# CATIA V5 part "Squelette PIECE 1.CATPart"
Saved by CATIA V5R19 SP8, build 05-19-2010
Part number: Squelette PIECE 1
Publications: "Droite.3", "Droite.2", "Droite.1", "Plan.1", "Point.6", "Point.7"
Bounding box of the stored display mesh (mm): x -17 to 0, y 0 to 0, z 0 to 9
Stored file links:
  C:\Users\ThinkMotion\Desktop\EU_thinkMotion\iao\IAO_MMS_Groupe3\jbuffard\jbuffard\Squelette PIECE 1.CATPart
  C:\Users\ThinkMotion\Desktop\EU_thinkMotion\iao\IAO_MMS_Groupe3\jbuffard\jbuffard\Mecanisme a coulisse a quatre elements de la griffe d'une camera.CATProduct
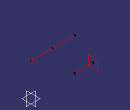
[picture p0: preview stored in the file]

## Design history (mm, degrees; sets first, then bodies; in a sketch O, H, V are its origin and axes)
Set1
  Point1 to Point5: linked copy from another document
  Plane1: linked copy from another document
Set2 "Set géométrique.3"
  Line1: type PtPt, FirstPoint Point1, SecondPoint Point2
  Line2: type PtPt, FirstPoint Point3, SecondPoint Point4
  Line3: type PtPt, FirstPoint Point4, SecondPoint Point5
  Plane2: type Offset, RefPlane Plane1, Offset 0
  Point6: type OnCurve, Support Line3, Ratio 0
  Point7: type OnCurve, Support Line3, Ratio 0.5
Body1 (main body)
